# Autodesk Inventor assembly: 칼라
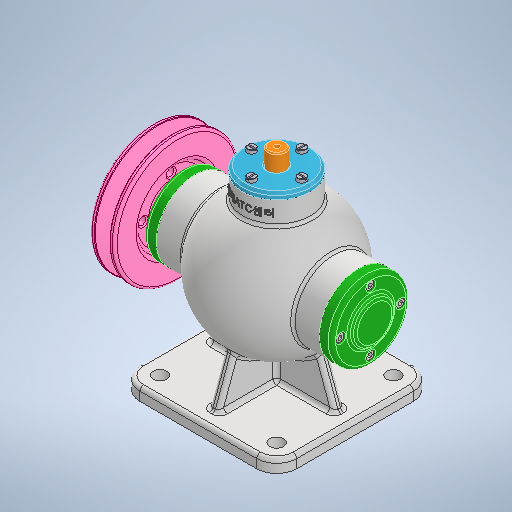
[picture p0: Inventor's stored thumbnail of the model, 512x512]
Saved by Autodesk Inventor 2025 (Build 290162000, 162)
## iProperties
Created: 2024-07
Part Number: 칼라
Material: 스테인리스강
Document SubType Name: Modeling
Designer: song
Density: 8.08 g/cm^3
Appearance: 기본값
Sending System: Autodesk Inventor 2025
Preprocessor: ST-DEVELOPER v20
Author: jhkim
Part Number: 너트 M8
Description: 플랜지붙이 6각 너트 - 일반 스레드
Density: 8 g/cm^3
Part Number: 슬라이드
Material: 강철, 연강
Density: 7.86 g/cm^3
Part Number: 앞커버
Material: 알루미늄 6061
Density: 2.71 g/cm^3
Part Number: 볼트 M4 x 12
Description: 6각머리 태핑 나사
Density: 7.85 g/cm^3
Part Number: 볼트 M4 x 16
Description: 6각 소켓 머리 캡 나사
Part Number: 편심축
Part Number: V-벨트풀리
Part Number: 오일실 15 30 7
Material: 고무
Description: 오일-실
Density: 0.93 g/cm^3
Part Number: 상부커버
Part Number: 뒤커버
Part Number: 키 4 x 4 x 12
Description: 키 및 해당 키홈
Part Number: 베어링 - 6202
Material: 강, 연강
Description: 깊은 그루브 볼 베어링
Part Number: 조립품
Document SubType Name: Assembly
Author: song
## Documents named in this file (28)
- **C:\Users\shmin\OneDrive\바탕 화면\740708V1008\조립품.iam*LocalDocs*xAaaaawbaAaaaaaaaAaaaq23uXb*칼라.ipt
- **C:\Users\shmin\OneDrive\바탕 화면\740708V1008\조립품.iam*LocalDocs*xAaaaajbaAaaaaaaaAaaaqnmbYh*너트 M8.ipt
- **C:\Users\shmin\OneDrive\바탕 화면\740708V1008\조립품.iam*LocalDocs*xAaaaaadaAaaaaaaaAaaaazvgZd*슬라이드.ipt
- **C:\Users\shmin\OneDrive\바탕 화면\740708V1008\조립품.iam*LocalDocs*xAaaaa3aaAaaaaaaaAaaaq03eNd*앞커버.ipt
- **C:\Users\shmin\OneDrive\바탕 화면\740708V1008\조립품.iam*LocalDocs*xAaaaacaaAaaaaaaaAaaaa3h5Ga*볼트 M4 x 12.ipt
- **C:\Users\shmin\OneDrive\바탕 화면\740708V1008\조립품.iam*LocalDocs*xAaaaapcaAaaaaaaaAaaaac1wAh*볼트 M4 x 16.ipt
- **C:\Users\shmin\OneDrive\바탕 화면\740708V1008\조립품.iam*LocalDocs*xAaaaq0daAaaaaaaaAaaaqx2wAf*편심축.ipt
- **C:\Users\shmin\OneDrive\바탕 화면\740708V1008\조립품.iam*LocalDocs*xAaaaq0baAaaaaaaaAaaaa5n3Dh*V-벨트풀리.ipt
- **C:\Users\shmin\OneDrive\바탕 화면\740708V1008\조립품.iam*LocalDocs*xAaaaqmaaAaaaaaaaAaaaqevtHc*오일실 15 30 7.ipt
- **C:\Users\shmin\OneDrive\바탕 화면\740708V1008\조립품.iam*LocalDocs*xAaaaqkbaAaaaaaaaAaaaaxicRh*상부커버.ipt
- **C:\Users\shmin\OneDrive\바탕 화면\740708V1008\조립품.iam*LocalDocs*xAaaaqrcaAaaaaaaaAaaaahqyVe*뒤커버.ipt
- **C:\Users\shmin\OneDrive\바탕 화면\740708V1008\조립품.iam*LocalDocs*xAaaaqndaAaaaaaaaAaaaqdlgRa*키 4 x 4 x 12.ipt
- **C:\Users\shmin\OneDrive\바탕 화면\740708V1008\조립품.iam*LocalDocs*xAaaaqxdaAaaaaaaaAaaaq2nzIb*베어링- 6202.ipt
- C:\Users\shmin\OneDrive\바탕 화면\740708V1008\조립품.iam
- C:\Users\shmin\OneDrive\바탕 화면\740708V1008\본체.ipt
- C:\Users\shmin\OneDrive\바탕 화면\740708V1008\뒤커버.stp
- C:\Users\shmin\OneDrive\바탕 화면\740708V1008\볼트 M4 x 16.stp
- C:\Users\shmin\OneDrive\바탕 화면\740708V1008\앞커버.stp
- C:\Users\shmin\OneDrive\바탕 화면\740708V1008\상부커버.stp
- C:\Users\shmin\OneDrive\바탕 화면\740708V1008\볼트 M4 x 12.stp
- C:\Users\shmin\OneDrive\바탕 화면\740708V1008\베어링- 6202.stp
- C:\Users\shmin\OneDrive\바탕 화면\740708V1008\오일실 15 30 7.stp
- C:\Users\shmin\OneDrive\바탕 화면\740708V1008\편심축.stp
- C:\Users\shmin\OneDrive\바탕 화면\740708V1008\칼라.stp
- C:\Users\shmin\OneDrive\바탕 화면\740708V1008\키 4 x 4 x 12.stp
- C:\Users\shmin\OneDrive\바탕 화면\740708V1008\V-벨트풀리.stp
- C:\Users\shmin\OneDrive\바탕 화면\740708V1008\슬라이드.stp
- C:\Users\shmin\OneDrive\바탕 화면\740708V1008\너트 M8.stp
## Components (1 placed, 1 different names)
1. V-벨트풀리:1
